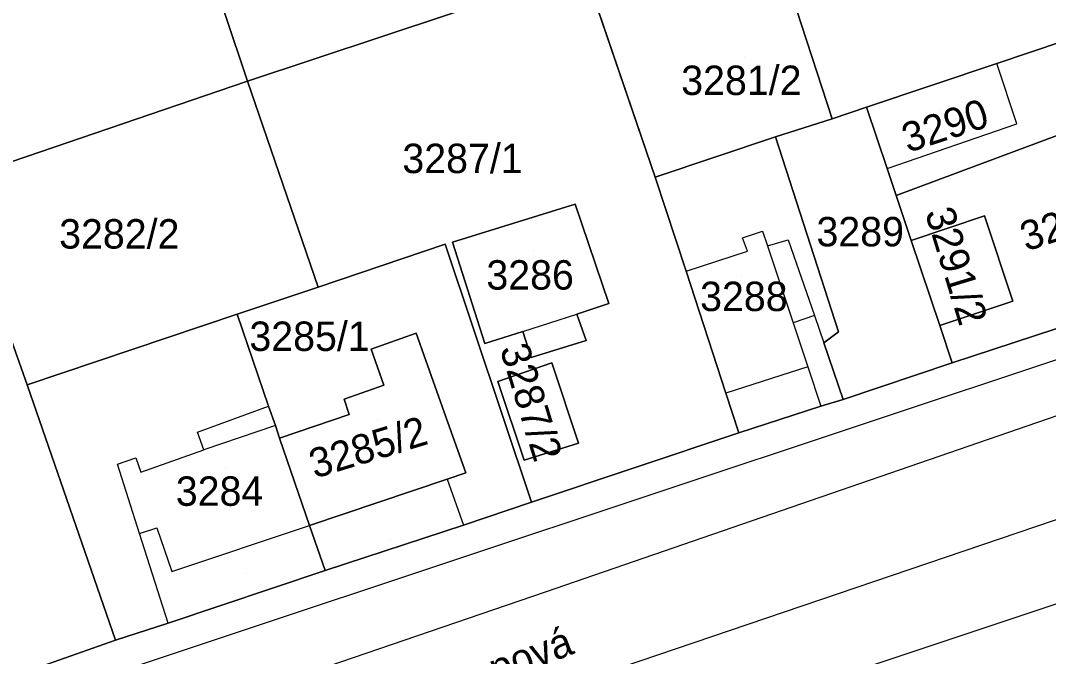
# Model space of a CAD drawing. Extents: x -262657 to -261595, y -1238015 to -1237156.
# Drawn here: x -261809.5 to -261739.6, y -1237919.8 to -1237876.6 of the extents above; entities that cross this region are included whole.
import ezdxf

# ---------------------------------------------------------------- set-up
doc = ezdxf.new("R2010")
doc.units = 0
for name, color, linetype in [('body_kn', 7, 'Continuous'), ('kladpar_druhypozemkov', 7, 'Continuous'), ('kladpar_hranice', 7, 'Continuous'), ('kladpar_parcelnecisla', 7, 'Continuous'), ('kladpar_plochy', 7, 'Continuous'), ('popisy', 7, 'Continuous'), ('zappar_hrandruhpozemk', 7, 'Continuous')]:
    doc.layers.add(name, color=color, linetype=linetype)

msp = doc.modelspace()

# ---------------------------------------------------------------- linework, layer by layer
at = {"layer": 'body_kn'}
for p, q in [((-261743.11, -1237879.52), (-261743.11, -1237879.52)), ((-261794.07, -1237880.71), (-261794.07, -1237880.71)), ((-261794.07, -1237880.71), (-261794.07, -1237880.71)), ((-261751.96, -1237882.49), (-261751.96, -1237882.49)), ((-261754.31, -1237883.27), (-261754.31, -1237883.27)), ((-261741.75, -1237883.63), (-261741.75, -1237883.63)), ((-261758.16, -1237884.5), (-261758.16, -1237884.5)), ((-261750.56, -1237886.65), (-261750.56, -1237886.65)), ((-261750.56, -1237886.65), (-261750.56, -1237886.65)), ((-261766.33, -1237887.24), (-261766.33, -1237887.24)), ((-261749.95, -1237888.49), (-261749.95, -1237888.49)), ((-261771.79, -1237889.07), (-261771.79, -1237889.07)), ((-261743.94, -1237889.88), (-261743.94, -1237889.88)), ((-261760.41, -1237891.37), (-261760.41, -1237891.37)), ((-261759.03, -1237890.91), (-261759.03, -1237890.91)), ((-261757.29, -1237891.5), (-261757.29, -1237891.5)), ((-261748.93, -1237891.55), (-261748.93, -1237891.55)), ((-261748.93, -1237891.55), (-261748.93, -1237891.55)), ((-261780.62, -1237891.81), (-261780.62, -1237891.81)), ((-261780.13, -1237891.66), (-261780.13, -1237891.66)), ((-261760.06, -1237892.27), (-261760.06, -1237892.27)), ((-261758.69, -1237891.92), (-261758.69, -1237891.92)), ((-261764.24, -1237893.64), (-261764.24, -1237893.64)), ((-261764.24, -1237893.64), (-261764.24, -1237893.64)), ((-261789.26, -1237894.72), (-261789.26, -1237894.72)), ((-261742.01, -1237895.67), (-261742.01, -1237895.67)), ((-261769.49, -1237895.84), (-261769.49, -1237895.84)), ((-261794.77, -1237896.57), (-261794.77, -1237896.57)), ((-261771.67, -1237896.56), (-261771.67, -1237896.56)), ((-261756.95, -1237897.15), (-261756.95, -1237897.15)), ((-261756.95, -1237897.15), (-261756.95, -1237897.15)), ((-261755.51, -1237896.65), (-261755.51, -1237896.65)), ((-261782.6, -1237897.86), (-261782.6, -1237897.86)), ((-261775.34, -1237897.74), (-261775.34, -1237897.74)), ((-261775.34, -1237897.74), (-261775.34, -1237897.74)), ((-261753.87, -1237897.77), (-261753.87, -1237897.77)), ((-261746.98, -1237897.34), (-261746.98, -1237897.34)), ((-261777.92, -1237898.56), (-261777.92, -1237898.56)), ((-261777.92, -1237898.56), (-261777.92, -1237898.56)), ((-261771.03, -1237898.35), (-261771.03, -1237898.35)), ((-261754.88, -1237898.5), (-261754.88, -1237898.5)), ((-261785.66, -1237898.95), (-261785.66, -1237898.95)), ((-261781.94, -1237899.7), (-261781.94, -1237899.7)), ((-261774.78, -1237899.5), (-261774.78, -1237899.5)), ((-261773.37, -1237899.87), (-261773.37, -1237899.87)), ((-261746.14, -1237899.86), (-261746.14, -1237899.86)), ((-261746.14, -1237899.86), (-261746.14, -1237899.86)), ((-261755.96, -1237900.14), (-261755.96, -1237900.14)), ((-261809.06, -1237901.36), (-261809.06, -1237901.36)), ((-261777.04, -1237901.13), (-261777.04, -1237901.13)), ((-261784.8, -1237901.39), (-261784.8, -1237901.39)), ((-261761.54, -1237901.92), (-261761.54, -1237901.92)), ((-261787.49, -1237902.34), (-261787.49, -1237902.34)), ((-261753.55, -1237902.35), (-261753.55, -1237902.35)), ((-261753.55, -1237902.35), (-261753.55, -1237902.35)), ((-261792.63, -1237902.81), (-261792.63, -1237902.81)), ((-261787.14, -1237903.38), (-261787.14, -1237903.38)), ((-261755.07, -1237902.82), (-261755.07, -1237902.82)), ((-261792.17, -1237904.13), (-261792.17, -1237904.13)), ((-261792.17, -1237904.13), (-261792.17, -1237904.13)), ((-261797.47, -1237904.59), (-261797.47, -1237904.59)), ((-261780.32, -1237904.24), (-261780.32, -1237904.24)), ((-261760.66, -1237904.62), (-261760.66, -1237904.62)), ((-261791.88, -1237905), (-261791.88, -1237905)), ((-261771.56, -1237905.33), (-261771.56, -1237905.33)), ((-261771.56, -1237905.33), (-261771.56, -1237905.33)), ((-261797.03, -1237905.78), (-261797.03, -1237905.78)), ((-261797.03, -1237905.78), (-261797.03, -1237905.78)), ((-261802.91, -1237906.75), (-261802.91, -1237906.75)), ((-261801.67, -1237906.33), (-261801.67, -1237906.33)), ((-261775.24, -1237906.48), (-261775.24, -1237906.48)), ((-261801.32, -1237907.31), (-261801.32, -1237907.31)), ((-261779.21, -1237907.35), (-261779.21, -1237907.35)), ((-261780.48, -1237907.78), (-261780.48, -1237907.78)), ((-261780.48, -1237907.78), (-261780.48, -1237907.78)), ((-261774.74, -1237909.35), (-261774.74, -1237909.35)), ((-261800.22, -1237911.08), (-261800.22, -1237911.08)), ((-261789.84, -1237910.93), (-261789.84, -1237910.93)), ((-261789.84, -1237910.93), (-261789.84, -1237910.93)), ((-261779.37, -1237910.9), (-261779.37, -1237910.9)), ((-261801.4, -1237911.48), (-261801.4, -1237911.48)), ((-261799.21, -1237914.06), (-261799.21, -1237914.06)), ((-261788.79, -1237913.99), (-261788.79, -1237913.99)), ((-261788.79, -1237913.99), (-261788.79, -1237913.99)), ((-261773.83, -1237915.47), (-261773.83, -1237915.47)), ((-261799.45, -1237917.56), (-261799.45, -1237917.56)), ((-261799.45, -1237917.56), (-261799.45, -1237917.56)), ((-261794.68, -1237918.16), (-261794.68, -1237918.16)), ((-261803.05, -1237918.72), (-261803.05, -1237918.72))]:
    msp.add_line(p, q, dxfattribs=at)
at = {"layer": 'kladpar_druhypozemkov'}
for p, q in [((-261760.29, -1237879.13), (-261760.29, -1237879.13)), ((-261746.91, -1237882.7), (-261746.91, -1237882.7)), ((-261779.67, -1237884.79), (-261779.67, -1237884.79)), ((-261801.44, -1237889.9), (-261801.44, -1237889.9)), ((-261752.02, -1237890.49), (-261752.02, -1237890.49)), ((-261774.59, -1237892.22), (-261774.59, -1237892.22)), ((-261744.65, -1237893.42), (-261744.65, -1237893.42)), ((-261760.5, -1237894.01), (-261760.5, -1237894.01)), ((-261790.21, -1237897.49), (-261790.21, -1237897.49)), ((-261773.6, -1237903.01), (-261773.6, -1237903.01)), ((-261785.22, -1237903.82), (-261785.22, -1237903.82)), ((-261795.58, -1237907), (-261795.58, -1237907)), ((-261784.34, -1237911.89), (-261784.34, -1237911.89)), ((-261794.15, -1237914.21), (-261794.15, -1237914.21))]:
    msp.add_line(p, q, dxfattribs=at)
at = {"layer": 'kladpar_hranice'}
msp.add_line((-261774.74, -1237909.35), (-261780.62, -1237891.81), dxfattribs=at)
for points in [[(-261771.16, -1237873.1), (-261794.07, -1237880.71), (-261798.67, -1237866.97), (-261780.5, -1237860.43), (-261777.9, -1237869.36), (-261759.82, -1237863.8), (-261759.74, -1237861.28), (-261743.44, -1237855.99), (-261741.18, -1237862.67), (-261748.24, -1237865.13), (-261758.97, -1237868.92), (-261762.82, -1237870.21), (-261765.22, -1237871.09), (-261771.16, -1237873.1)], [(-261736.31, -1237877.23), (-261743.11, -1237879.52), (-261751.96, -1237882.49), (-261754.31, -1237883.27), (-261757.41, -1237873.74), (-261746.57, -1237869.99), (-261748.24, -1237865.13), (-261741.18, -1237862.67), (-261736.31, -1237877.23)], [(-261794.07, -1237880.71), (-261813.88, -1237887.48), (-261836.71, -1237895.38), (-261842.22, -1237882.31), (-261836.71, -1237880.35), (-261798.67, -1237866.97), (-261794.07, -1237880.71)], [(-261757.55, -1237873.3), (-261757.41, -1237873.74), (-261754.31, -1237883.27), (-261758.16, -1237884.5), (-261766.33, -1237887.24), (-261771.16, -1237873.1), (-261765.22, -1237871.09), (-261763.85, -1237874.99), (-261761.44, -1237874.17), (-261761.26, -1237874.63), (-261757.55, -1237873.3)], [(-261794.07, -1237880.71), (-261771.16, -1237873.1), (-261766.33, -1237887.24), (-261764.24, -1237893.64), (-261761.54, -1237901.92), (-261760.66, -1237904.62), (-261774.74, -1237909.35)], [(-261736.31, -1237877.23), (-261734.52, -1237882.73), (-261749.95, -1237888.49), (-261750.56, -1237886.65), (-261751.96, -1237882.49), (-261743.11, -1237879.52), (-261736.31, -1237877.23)], [(-261794.07, -1237880.71), (-261789.26, -1237894.72), (-261794.77, -1237896.57), (-261809.06, -1237901.36), (-261810.24, -1237897.97), (-261813.88, -1237887.48), (-261794.07, -1237880.71)], [(-261780.62, -1237891.81), (-261789.26, -1237894.72), (-261794.07, -1237880.71)], [(-261746.14, -1237899.86), (-261753.55, -1237902.35), (-261754.88, -1237898.5), (-261753.87, -1237897.77), (-261758.16, -1237884.5), (-261754.31, -1237883.27), (-261751.96, -1237882.49), (-261750.56, -1237886.65), (-261749.95, -1237888.49), (-261748.93, -1237891.55), (-261746.98, -1237897.34), (-261746.14, -1237899.86)], [(-261733.49, -1237895.72), (-261746.14, -1237899.86), (-261746.98, -1237897.34), (-261742.01, -1237895.67), (-261743.94, -1237889.88), (-261748.93, -1237891.55), (-261749.95, -1237888.49), (-261734.52, -1237882.73), (-261732.32, -1237889.37), (-261733.49, -1237895.72)], [(-261753.55, -1237902.35), (-261755.07, -1237902.82), (-261760.66, -1237904.62), (-261761.54, -1237901.92), (-261764.24, -1237893.64), (-261766.33, -1237887.24), (-261758.16, -1237884.5), (-261753.87, -1237897.77), (-261754.88, -1237898.5), (-261753.55, -1237902.35)], [(-261777.92, -1237898.56), (-261780.13, -1237891.66), (-261771.79, -1237889.07), (-261769.49, -1237895.84), (-261771.67, -1237896.56), (-261771.03, -1237898.35), (-261774.78, -1237899.5), (-261775.34, -1237897.74), (-261777.92, -1237898.56)], [(-261780.13, -1237891.66), (-261777.92, -1237898.56), (-261775.34, -1237897.74), (-261774.78, -1237899.5), (-261771.03, -1237898.35), (-261771.67, -1237896.56), (-261769.49, -1237895.84), (-261771.79, -1237889.07), (-261780.13, -1237891.66)], [(-261748.93, -1237891.55), (-261743.94, -1237889.88), (-261742.01, -1237895.67), (-261746.98, -1237897.34), (-261748.93, -1237891.55)], [(-261788.79, -1237913.99), (-261789.84, -1237910.93), (-261780.48, -1237907.78), (-261779.21, -1237907.35), (-261780.32, -1237904.24), (-261781.94, -1237899.7), (-261782.6, -1237897.86), (-261785.66, -1237898.95), (-261784.8, -1237901.39), (-261787.49, -1237902.34), (-261787.14, -1237903.38), (-261791.88, -1237905), (-261792.17, -1237904.13), (-261792.63, -1237902.81), (-261794.77, -1237896.57), (-261789.26, -1237894.72), (-261780.62, -1237891.81), (-261774.74, -1237909.35), (-261779.37, -1237910.9), (-261788.79, -1237913.99)], [(-261855.91, -1237931.48), (-261845.09, -1237931.42), (-261843.87, -1237931.41), (-261843.16, -1237932.9), (-261841.21, -1237931.96), (-261841.47, -1237931.4), (-261838.86, -1237931.38), (-261836.77, -1237930.66), (-261836.23, -1237930.47), (-261826.55, -1237927.03), (-261823.67, -1237926.01), (-261815.02, -1237922.93), (-261803.05, -1237918.72), (-261799.45, -1237917.56), (-261788.79, -1237913.99), (-261779.37, -1237910.9), (-261774.74, -1237909.35), (-261760.66, -1237904.62), (-261755.07, -1237902.82), (-261753.55, -1237902.35), (-261746.14, -1237899.86), (-261733.49, -1237895.72)], [(-261788.79, -1237913.99), (-261799.45, -1237917.56), (-261803.05, -1237918.72), (-261809.06, -1237901.36), (-261794.77, -1237896.57), (-261792.63, -1237902.81), (-261792.17, -1237904.13), (-261791.88, -1237905), (-261789.84, -1237910.93), (-261788.79, -1237913.99)], [(-261789.84, -1237910.93), (-261791.88, -1237905), (-261787.14, -1237903.38), (-261787.49, -1237902.34), (-261784.8, -1237901.39), (-261785.66, -1237898.95), (-261782.6, -1237897.86), (-261781.94, -1237899.7), (-261780.32, -1237904.24), (-261779.21, -1237907.35), (-261780.48, -1237907.78), (-261789.84, -1237910.93)], [(-261850.36, -1237911.93), (-261810.24, -1237897.97), (-261809.06, -1237901.36), (-261803.05, -1237918.72), (-261815.02, -1237922.93), (-261821.85, -1237902.91), (-261824.12, -1237903.73), (-261828.03, -1237905.14), (-261831.51, -1237906.62), (-261831.81, -1237905.77), (-261846.35, -1237910.75), (-261844.49, -1237916.47), (-261844.37, -1237916.85), (-261843.84, -1237918.59), (-261847.03, -1237919.51), (-261849.36, -1237914.23), (-261850.36, -1237911.93)], [(-261771.56, -1237905.33), (-261775.24, -1237906.48), (-261777.04, -1237901.13), (-261773.37, -1237899.87), (-261771.56, -1237905.33)], [(-261775.24, -1237906.48), (-261771.56, -1237905.33), (-261773.37, -1237899.87), (-261777.04, -1237901.13), (-261775.24, -1237906.48)], [(-261727.99, -1237912.57), (-261763.54, -1237924.41), (-261786.15, -1237931.76), (-261793.04, -1237934.21), (-261822.63, -1237945.17), (-261832.88, -1237949.98), (-261834.67, -1237950.82), (-261857.62, -1237961.58), (-261876.1, -1237970.13), (-261879.42, -1237971.62), (-261885.86, -1237974.51), (-261889.63, -1237976.21), (-261941.87, -1237999.81), (-261949.48, -1238002.8), (-261968.18, -1238010.15), (-261970.85, -1238012.16), (-261972.53, -1238015.11), (-261973.89, -1238014.34), (-261981.54, -1238009.7), (-261992.4, -1238009.93), (-261991.11, -1238000.48), (-261996, -1238000.09), (-261995.78, -1237991.95), (-261995.49, -1237985.74)]]:
    msp.add_lwpolyline(points, dxfattribs=at)
at = {"layer": 'kladpar_plochy'}
for p, q in [((-261794.07, -1237880.71), (-261771.16, -1237873.1)), ((-261771.16, -1237873.1), (-261766.33, -1237887.24)), ((-261789.26, -1237894.72), (-261794.07, -1237880.71)), ((-261766.33, -1237887.24), (-261764.24, -1237893.64)), ((-261771.79, -1237889.07), (-261780.13, -1237891.66)), ((-261769.49, -1237895.84), (-261771.79, -1237889.07)), ((-261780.62, -1237891.81), (-261789.26, -1237894.72)), ((-261774.74, -1237909.35), (-261780.62, -1237891.81)), ((-261780.13, -1237891.66), (-261777.92, -1237898.56)), ((-261764.24, -1237893.64), (-261761.54, -1237901.92)), ((-261771.67, -1237896.56), (-261769.49, -1237895.84)), ((-261771.03, -1237898.35), (-261771.67, -1237896.56)), ((-261777.92, -1237898.56), (-261775.34, -1237897.74)), ((-261775.34, -1237897.74), (-261774.78, -1237899.5)), ((-261774.78, -1237899.5), (-261771.03, -1237898.35)), ((-261773.37, -1237899.87), (-261777.04, -1237901.13)), ((-261771.56, -1237905.33), (-261773.37, -1237899.87)), ((-261777.04, -1237901.13), (-261775.24, -1237906.48)), ((-261761.54, -1237901.92), (-261760.66, -1237904.62)), ((-261760.66, -1237904.62), (-261774.74, -1237909.35)), ((-261775.24, -1237906.48), (-261771.56, -1237905.33))]:
    msp.add_line(p, q, dxfattribs=at)
for points in [[(-261771.16, -1237873.1), (-261794.07, -1237880.71), (-261798.67, -1237866.97), (-261780.5, -1237860.43), (-261777.9, -1237869.36), (-261759.82, -1237863.8), (-261759.74, -1237861.28), (-261743.44, -1237855.99), (-261741.18, -1237862.67), (-261748.24, -1237865.13), (-261758.97, -1237868.92), (-261762.82, -1237870.21), (-261765.22, -1237871.09)], [(-261736.31, -1237877.23), (-261743.11, -1237879.52), (-261751.96, -1237882.49), (-261754.31, -1237883.27), (-261757.41, -1237873.74), (-261746.57, -1237869.99), (-261748.24, -1237865.13), (-261741.18, -1237862.67)], [(-261794.07, -1237880.71), (-261813.88, -1237887.48), (-261836.71, -1237895.38), (-261842.22, -1237882.31), (-261836.71, -1237880.35), (-261798.67, -1237866.97)], [(-261757.55, -1237873.3), (-261757.41, -1237873.74), (-261754.31, -1237883.27), (-261758.16, -1237884.5), (-261766.33, -1237887.24), (-261771.16, -1237873.1), (-261765.22, -1237871.09), (-261763.85, -1237874.99), (-261761.44, -1237874.17), (-261761.26, -1237874.63)], [(-261736.31, -1237877.23), (-261734.52, -1237882.73), (-261749.95, -1237888.49), (-261750.56, -1237886.65), (-261751.96, -1237882.49), (-261743.11, -1237879.52)], [(-261794.07, -1237880.71), (-261789.26, -1237894.72), (-261794.77, -1237896.57), (-261809.06, -1237901.36), (-261810.24, -1237897.97), (-261813.88, -1237887.48)], [(-261746.14, -1237899.86), (-261753.55, -1237902.35), (-261754.88, -1237898.5), (-261753.87, -1237897.77), (-261758.16, -1237884.5), (-261754.31, -1237883.27), (-261751.96, -1237882.49), (-261750.56, -1237886.65), (-261749.95, -1237888.49), (-261748.93, -1237891.55), (-261746.98, -1237897.34)], [(-261733.49, -1237895.72), (-261746.14, -1237899.86), (-261746.98, -1237897.34), (-261742.01, -1237895.67), (-261743.94, -1237889.88), (-261748.93, -1237891.55), (-261749.95, -1237888.49), (-261734.52, -1237882.73), (-261732.32, -1237889.37)], [(-261753.55, -1237902.35), (-261755.07, -1237902.82), (-261760.66, -1237904.62), (-261761.54, -1237901.92), (-261764.24, -1237893.64), (-261766.33, -1237887.24), (-261758.16, -1237884.5), (-261753.87, -1237897.77), (-261754.88, -1237898.5)], [(-261777.92, -1237898.56), (-261780.13, -1237891.66), (-261771.79, -1237889.07), (-261769.49, -1237895.84), (-261771.67, -1237896.56), (-261771.03, -1237898.35), (-261774.78, -1237899.5), (-261775.34, -1237897.74)], [(-261748.93, -1237891.55), (-261743.94, -1237889.88), (-261742.01, -1237895.67), (-261746.98, -1237897.34)], [(-261788.79, -1237913.99), (-261789.84, -1237910.93), (-261780.48, -1237907.78), (-261779.21, -1237907.35), (-261780.32, -1237904.24), (-261781.94, -1237899.7), (-261782.6, -1237897.86), (-261785.66, -1237898.95), (-261784.8, -1237901.39), (-261787.49, -1237902.34), (-261787.14, -1237903.38), (-261791.88, -1237905), (-261792.17, -1237904.13), (-261792.63, -1237902.81), (-261794.77, -1237896.57), (-261789.26, -1237894.72), (-261780.62, -1237891.81), (-261774.74, -1237909.35), (-261779.37, -1237910.9)], [(-261788.79, -1237913.99), (-261799.45, -1237917.56), (-261803.05, -1237918.72), (-261809.06, -1237901.36), (-261794.77, -1237896.57), (-261792.63, -1237902.81), (-261792.17, -1237904.13), (-261791.88, -1237905), (-261789.84, -1237910.93)], [(-261789.84, -1237910.93), (-261791.88, -1237905), (-261787.14, -1237903.38), (-261787.49, -1237902.34), (-261784.8, -1237901.39), (-261785.66, -1237898.95), (-261782.6, -1237897.86), (-261781.94, -1237899.7), (-261780.32, -1237904.24), (-261779.21, -1237907.35), (-261780.48, -1237907.78)], [(-261850.36, -1237911.93), (-261810.24, -1237897.97), (-261809.06, -1237901.36), (-261803.05, -1237918.72), (-261815.02, -1237922.93), (-261821.85, -1237902.91), (-261824.12, -1237903.73), (-261828.03, -1237905.14), (-261831.51, -1237906.62), (-261831.81, -1237905.77), (-261846.35, -1237910.75), (-261844.49, -1237916.47), (-261844.37, -1237916.85), (-261843.84, -1237918.59), (-261847.03, -1237919.51), (-261849.36, -1237914.23)], [(-261771.56, -1237905.33), (-261775.24, -1237906.48), (-261777.04, -1237901.13), (-261773.37, -1237899.87)]]:
    msp.add_lwpolyline(points, close=True, dxfattribs=at)
for points in [[(-261855.91, -1237931.48), (-261845.09, -1237931.42), (-261843.87, -1237931.41), (-261843.16, -1237932.9), (-261841.21, -1237931.96), (-261841.47, -1237931.4), (-261838.86, -1237931.38), (-261836.77, -1237930.66), (-261836.23, -1237930.47), (-261826.55, -1237927.03), (-261823.67, -1237926.01), (-261815.02, -1237922.93), (-261803.05, -1237918.72), (-261799.45, -1237917.56), (-261788.79, -1237913.99), (-261779.37, -1237910.9), (-261774.74, -1237909.35), (-261760.66, -1237904.62), (-261755.07, -1237902.82), (-261753.55, -1237902.35), (-261746.14, -1237899.86), (-261733.49, -1237895.72)], [(-261727.99, -1237912.57), (-261763.54, -1237924.41), (-261786.15, -1237931.76), (-261793.04, -1237934.21), (-261822.63, -1237945.17), (-261832.88, -1237949.98), (-261834.67, -1237950.82), (-261857.62, -1237961.58)]]:
    msp.add_lwpolyline(points, dxfattribs=at)
at = {"layer": 'zappar_hrandruhpozemk'}
for p, q in [((-261640.4, -1237877.01), (-261795.73, -1237929.79)), ((-261741.75, -1237883.63), (-261743.11, -1237879.52)), ((-261750.56, -1237886.65), (-261741.75, -1237883.63)), ((-261758.69, -1237891.92), (-261757.29, -1237891.5)), ((-261757.29, -1237891.5), (-261755.51, -1237896.65)), ((-261758.69, -1237891.92), (-261756.95, -1237897.15)), ((-261794.68, -1237918.16), (-261726.26, -1237895.38)), ((-261794.68, -1237918.16), (-261726.26, -1237895.38)), ((-261775.34, -1237897.74), (-261771.67, -1237896.56)), ((-261755.51, -1237896.65), (-261756.95, -1237897.15)), ((-261756.95, -1237897.15), (-261755.96, -1237900.14)), ((-261755.51, -1237896.65), (-261754.88, -1237898.5)), ((-261755.96, -1237900.14), (-261761.54, -1237901.92)), ((-261755.96, -1237900.14), (-261755.07, -1237902.82)), ((-261797.47, -1237904.59), (-261792.63, -1237902.81)), ((-261792.17, -1237904.13), (-261797.03, -1237905.78)), ((-261797.03, -1237905.78), (-261797.47, -1237904.59)), ((-261801.32, -1237907.31), (-261797.03, -1237905.78)), ((-261780.48, -1237907.78), (-261779.37, -1237910.9)), ((-261799.21, -1237914.06), (-261789.84, -1237910.93)), ((-261799.45, -1237917.56), (-261801.4, -1237911.48)), ((-261773.83, -1237915.47), (-261840.93, -1237938.33))]:
    msp.add_line(p, q, dxfattribs=at)
for points in [[(-261764.24, -1237893.64), (-261760.06, -1237892.27), (-261760.41, -1237891.37), (-261759.03, -1237890.91), (-261758.69, -1237891.92)], [(-261726.26, -1237895.38), (-261725.46, -1237897.29), (-261728.96, -1237900), (-261773.83, -1237915.47)], [(-261801.4, -1237911.48), (-261802.91, -1237906.75), (-261801.67, -1237906.33), (-261801.32, -1237907.31)], [(-261801.4, -1237911.48), (-261800.22, -1237911.08), (-261799.21, -1237914.06)], [(-261835.66, -1237933.61), (-261836.26, -1237931.97), (-261794.68, -1237918.16)], [(-261835.66, -1237933.61), (-261836.26, -1237931.97), (-261794.68, -1237918.16)]]:
    msp.add_lwpolyline(points, dxfattribs=at)

# ---------------------------------------------------------------- texts
at = {"layer": 'kladpar_parcelnecisla'}
for s, p in [('3281/2', (-261764.568, -1237881.66)), ('3287/1', (-261783.534, -1237886.97)), ('3282/2', (-261806.874, -1237892.1)), ('3289', (-261755.37, -1237891.95)), ('3286', (-261777.82, -1237894.89)), ('3288', (-261763.284, -1237896.35)), ('3285/1', (-261793.936, -1237899.06)), ('3284', (-261798.94, -1237909.59))]:
    msp.add_text(s, height=2, dxfattribs=at).set_placement(p)
for s, rotation, p in [('3290', 18, (-261749.158, -1237885.6)), ('3291/1', 18, (-261741.115, -1237892.305)), ('3291/2', 287, (-261748.005, -1237889.642)), ('3287/2', 287, (-261776.92, -1237898.906)), ('3285/2', 17, (-261789.492, -1237907.75))]:
    msp.add_text(s, height=2, rotation=rotation, dxfattribs=at).set_placement(p)
at = {"layer": 'popisy'}
msp.add_text('Rampová', height=2, rotation=21, dxfattribs=at).set_placement((-261782.437, -1237923.705))

doc.saveas('drawing.dxf')
